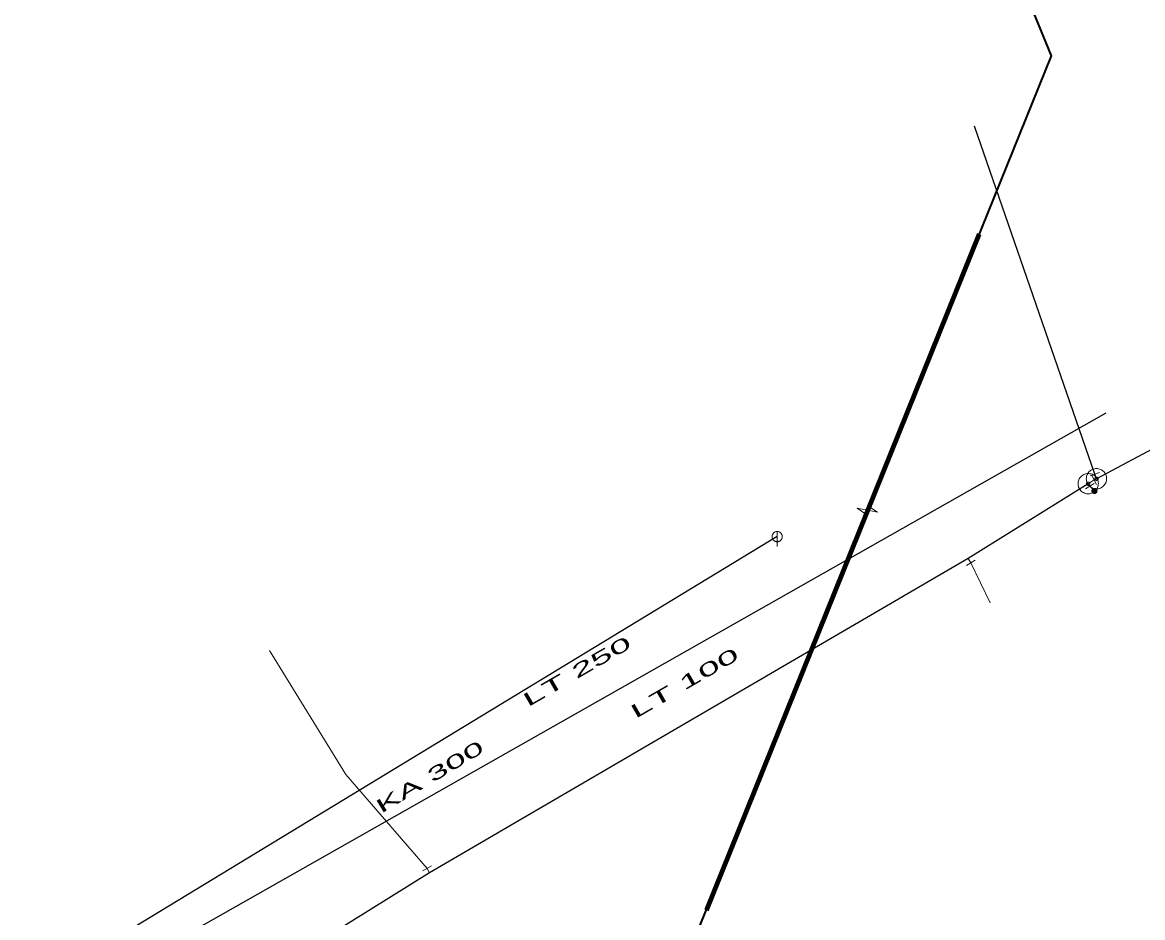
# Model space of a CAD drawing. Extents: x -687468 to -685917, y -974192 to -973456.
# Drawn here: x -686202 to -686146.9, y -973571.9 to -973527.9 of the extents above; entities that cross this region are included whole.
import ezdxf
from ezdxf.enums import TextEntityAlignment as Align

# ---------------------------------------------------------------- set-up
doc = ezdxf.new("R2010")
doc.units = 0
doc.header["$LTSCALE"] = 0.27
for name, color, linetype, lineweight in [('1', 7, 'Continuous', 13), ('13', 7, 'Continuous', 13), ('14', 7, 'Continuous', 25), ('17', 7, 'Continuous', 25), ('22', 7, 'Continuous', 13), ('3', 7, 'Continuous', 106), ('34', 7, 'Continuous', 13), ('47', 7, 'Continuous', 13), ('9', 7, 'Continuous', 13)]:
    doc.layers.add(name, color=color, linetype=linetype, lineweight=lineweight)

msp = doc.modelspace()

# ---------------------------------------------------------------- linework, layer by layer
at = {"layer": '13'}
msp.add_line((-686155.338, -973554.482), (-686154.39, -973556.449), dxfattribs=at)
msp.add_lwpolyline([(-686182.105, -973569.523), (-686186.109, -973564.899), (-686189.87, -973558.8)], dxfattribs=at)
at = {"layer": '14', "lineweight": 13}
for p, q in [((-686149.149, -973550.34), (-686149.229, -973550.109)), ((-686149.149, -973550.34), (-686149.259, -973550.399)), ((-686155.338, -973554.482), (-686155.47, -973554.27)), ((-686182.105, -973569.523), (-686181.98, -973569.739))]:
    msp.add_line(p, q, dxfattribs=at)
at = {"layer": '14'}
msp.add_line((-686164.87, -973553.19), (-686200.73, -973574.96), dxfattribs=at)
at = {"layer": '14', "lineweight": 13}
msp.add_lwpolyline([(-686149.259, -973550.399), (-686149.557, -973550.584), (-686149.48, -973550.709), (-686149.249, -973550.939)], dxfattribs=at)
at = {"layer": '17'}
msp.add_line((-686130.129, -973540.219), (-686149.149, -973550.34), dxfattribs=at)
at = {"layer": '17', "lineweight": 35}
for points in [[(-686159.37, -973510.05), (-686151.386, -973529.517), (-686160.425, -973551.891)], [(-686160.425, -973551.891), (-686169.469, -973574.282), (-686122.999, -973646.384), (-686098.932, -973712.353), (-686089.329, -973782.048), (-686297.791, -974027.806), (-686326.807, -974076.614), (-686379.703, -974100.561), (-686411.584, -974111.413)]]:
    msp.add_lwpolyline(points, dxfattribs=at)
at = {"layer": '17'}
for points in [[(-686149.149, -973550.34), (-686149.229, -973550.109), (-686155.149, -973532.979)], [(-686148.68, -973547.12), (-686199.359, -973575.84), (-686213.05, -973583.12), (-686218.669, -973575.249)], [(-686149.557, -973550.584), (-686155.469, -973554.27), (-686181.98, -973569.739), (-686198.489, -973580.019)]]:
    msp.add_lwpolyline(points, dxfattribs=at)
at = {"layer": '22'}
msp.add_line((-686164.869, -973552.938), (-686164.87, -973553.681), dxfattribs=at)
msp.add_lwpolyline([(-686164.618, -973553.19), (-686164.619, -973553.164), (-686164.623, -973553.138), (-686164.629, -973553.112), (-686164.639, -973553.088), (-686164.651, -973553.064), (-686164.665, -973553.042), (-686164.682, -973553.021), (-686164.7, -973553.003), (-686164.721, -973552.986), (-686164.743, -973552.972), (-686164.767, -973552.96), (-686164.791, -973552.95), (-686164.817, -973552.944), (-686164.843, -973552.94), (-686164.869, -973552.938), (-686164.895, -973552.939), (-686164.921, -973552.943), (-686164.947, -973552.949), (-686164.972, -973552.959), (-686164.995, -973552.971), (-686165.017, -973552.985), (-686165.038, -973553.002), (-686165.056, -973553.02), (-686165.073, -973553.041), (-686165.087, -973553.063), (-686165.099, -973553.087), (-686165.109, -973553.111), (-686165.116, -973553.137), (-686165.12, -973553.163), (-686165.122, -973553.189), (-686165.121, -973553.215), (-686165.117, -973553.241), (-686165.11, -973553.267), (-686165.1, -973553.292), (-686165.088, -973553.315), (-686165.074, -973553.337), (-686165.057, -973553.358), (-686165.039, -973553.376), (-686165.018, -973553.393), (-686164.996, -973553.407), (-686164.973, -973553.419), (-686164.948, -973553.429), (-686164.922, -973553.436), (-686164.896, -973553.44), (-686164.87, -973553.441), (-686164.844, -973553.441), (-686164.818, -973553.437), (-686164.792, -973553.43), (-686164.768, -973553.42), (-686164.744, -973553.408), (-686164.722, -973553.394), (-686164.701, -973553.377), (-686164.683, -973553.359), (-686164.666, -973553.338), (-686164.652, -973553.316), (-686164.64, -973553.293), (-686164.63, -973553.268), (-686164.624, -973553.242), (-686164.62, -973553.216)], close=True, dxfattribs=at)
at = {"layer": '3'}
msp.add_line((-686168.344, -973571.57), (-686154.923, -973538.295), dxfattribs=at)
at = {"layer": '3', "lineweight": 100}
msp.add_line((-686168.344, -973571.57), (-686154.923, -973538.295), dxfattribs=at)
at = {"layer": '34'}
for p, q in [((-686149.463, -973550.19), (-686148.994, -973550.027)), ((-686149.141, -973550.617), (-686149.376, -973550.18)), ((-686149.69, -973550.84), (-686149.269, -973550.577)), ((-686155.548, -973554.613), (-686155.127, -973554.35)), ((-686182.319, -973569.647), (-686181.89, -973569.398))]:
    msp.add_line(p, q, dxfattribs=at)
at = {"layer": '47'}
msp.add_line((-686160.925, -973551.794), (-686160.5, -973552.077), dxfattribs=at)
for points in [[(-686149.132, -973550.32), (-686149.162, -973550.277), (-686149.196, -973550.237), (-686149.234, -973550.202), (-686149.275, -973550.17), (-686149.32, -973550.143), (-686149.368, -973550.121), (-686149.417, -973550.104), (-686149.468, -973550.092), (-686149.52, -973550.085), (-686149.572, -973550.084), (-686149.625, -973550.088), (-686149.676, -973550.099), (-686149.726, -973550.113), (-686149.774, -973550.134), (-686149.82, -973550.159), (-686149.863, -973550.189), (-686149.903, -973550.223), (-686149.939, -973550.262), (-686149.97, -973550.302), (-686149.997, -973550.347), (-686150.019, -973550.395), (-686150.037, -973550.445), (-686150.049, -973550.496), (-686150.056, -973550.547), (-686150.056, -973550.599), (-686150.052, -973550.652), (-686150.042, -973550.704), (-686150.027, -973550.753), (-686150.006, -973550.801), (-686149.981, -973550.847), (-686149.951, -973550.89), (-686149.917, -973550.93), (-686149.879, -973550.966), (-686149.838, -973550.997), (-686149.793, -973551.024), (-686149.746, -973551.047), (-686149.696, -973551.064), (-686149.645, -973551.076), (-686149.593, -973551.083), (-686149.541, -973551.083), (-686149.488, -973551.079), (-686149.437, -973551.07), (-686149.387, -973551.054), (-686149.339, -973551.033), (-686149.293, -973551.008), (-686149.25, -973550.978), (-686149.21, -973550.944), (-686149.175, -973550.907), (-686149.143, -973550.865), (-686149.116, -973550.82), (-686149.093, -973550.773), (-686149.077, -973550.723), (-686149.065, -973550.672), (-686149.058, -973550.62), (-686149.057, -973550.568), (-686149.061, -973550.515), (-686149.071, -973550.465), (-686149.086, -973550.414), (-686149.107, -973550.366)], [(-686148.691, -973550.139), (-686148.714, -973550.092), (-686148.743, -973550.048), (-686148.775, -973550.008), (-686148.812, -973549.97), (-686148.853, -973549.937), (-686148.897, -973549.908), (-686148.943, -973549.885), (-686148.992, -973549.866), (-686149.042, -973549.851), (-686149.094, -973549.843), (-686149.146, -973549.839), (-686149.198, -973549.843), (-686149.25, -973549.85), (-686149.301, -973549.864), (-686149.349, -973549.882), (-686149.396, -973549.905), (-686149.44, -973549.934), (-686149.481, -973549.967), (-686149.518, -973550.003), (-686149.551, -973550.044), (-686149.58, -973550.088), (-686149.604, -973550.134), (-686149.623, -973550.183), (-686149.638, -973550.233), (-686149.645, -973550.285), (-686149.649, -973550.337), (-686149.646, -973550.39), (-686149.638, -973550.441), (-686149.624, -973550.492), (-686149.606, -973550.54), (-686149.583, -973550.587), (-686149.554, -973550.631), (-686149.522, -973550.673), (-686149.485, -973550.709), (-686149.444, -973550.742), (-686149.401, -973550.772), (-686149.354, -973550.796), (-686149.306, -973550.815), (-686149.255, -973550.829), (-686149.203, -973550.836), (-686149.151, -973550.84), (-686149.099, -973550.838), (-686149.047, -973550.829), (-686148.996, -973550.815), (-686148.948, -973550.797), (-686148.901, -973550.774), (-686148.857, -973550.745), (-686148.816, -973550.713), (-686148.779, -973550.676), (-686148.746, -973550.635), (-686148.716, -973550.592), (-686148.693, -973550.546), (-686148.674, -973550.497), (-686148.66, -973550.446), (-686148.652, -973550.394), (-686148.648, -973550.342), (-686148.651, -973550.29), (-686148.659, -973550.238), (-686148.673, -973550.187)], [(-686149.073, -973550.307), (-686149.077, -973550.298), (-686149.082, -973550.292), (-686149.087, -973550.285), (-686149.093, -973550.279), (-686149.1, -973550.273), (-686149.107, -973550.269), (-686149.115, -973550.265), (-686149.123, -973550.262), (-686149.131, -973550.26), (-686149.14, -973550.258), (-686149.148, -973550.258), (-686149.157, -973550.258), (-686149.165, -973550.259), (-686149.173, -973550.261), (-686149.181, -973550.264), (-686149.19, -973550.268), (-686149.196, -973550.273), (-686149.203, -973550.278), (-686149.209, -973550.284), (-686149.215, -973550.291), (-686149.219, -973550.298), (-686149.223, -973550.306), (-686149.226, -973550.314), (-686149.229, -973550.322), (-686149.23, -973550.331), (-686149.23, -973550.339), (-686149.23, -973550.348), (-686149.229, -973550.356), (-686149.227, -973550.364), (-686149.224, -973550.372), (-686149.22, -973550.381), (-686149.215, -973550.387), (-686149.21, -973550.394), (-686149.204, -973550.4), (-686149.197, -973550.406), (-686149.191, -973550.41), (-686149.182, -973550.414), (-686149.174, -973550.417), (-686149.166, -973550.42), (-686149.157, -973550.421), (-686149.149, -973550.421), (-686149.14, -973550.421), (-686149.132, -973550.42), (-686149.124, -973550.418), (-686149.116, -973550.415), (-686149.107, -973550.411), (-686149.101, -973550.406), (-686149.094, -973550.401), (-686149.088, -973550.395), (-686149.082, -973550.388), (-686149.078, -973550.382), (-686149.074, -973550.373), (-686149.071, -973550.365), (-686149.069, -973550.357), (-686149.067, -973550.348), (-686149.067, -973550.34), (-686149.067, -973550.331), (-686149.068, -973550.323), (-686149.07, -973550.315)], [(-686149.487, -973550.54), (-686149.492, -973550.533), (-686149.497, -973550.527), (-686149.503, -973550.521), (-686149.51, -973550.516), (-686149.518, -973550.511), (-686149.526, -973550.508), (-686149.534, -973550.505), (-686149.542, -973550.503), (-686149.551, -973550.502), (-686149.559, -973550.502), (-686149.568, -973550.502), (-686149.576, -973550.504), (-686149.584, -973550.507), (-686149.592, -973550.509), (-686149.6, -973550.514), (-686149.607, -973550.519), (-686149.613, -973550.524), (-686149.619, -973550.53), (-686149.624, -973550.537), (-686149.629, -973550.545), (-686149.632, -973550.553), (-686149.635, -973550.561), (-686149.637, -973550.569), (-686149.639, -973550.578), (-686149.638, -973550.586), (-686149.638, -973550.595), (-686149.636, -973550.603), (-686149.633, -973550.611), (-686149.631, -973550.619), (-686149.626, -973550.627), (-686149.621, -973550.634), (-686149.616, -973550.64), (-686149.61, -973550.646), (-686149.603, -973550.651), (-686149.595, -973550.656), (-686149.588, -973550.66), (-686149.579, -973550.662), (-686149.571, -973550.664), (-686149.562, -973550.666), (-686149.554, -973550.665), (-686149.545, -973550.665), (-686149.537, -973550.663), (-686149.529, -973550.66), (-686149.521, -973550.658), (-686149.513, -973550.653), (-686149.506, -973550.648), (-686149.5, -973550.643), (-686149.494, -973550.637), (-686149.489, -973550.63), (-686149.484, -973550.622), (-686149.48, -973550.615), (-686149.478, -973550.606), (-686149.476, -973550.598), (-686149.475, -973550.589), (-686149.475, -973550.581), (-686149.475, -973550.572), (-686149.477, -973550.564), (-686149.48, -973550.556), (-686149.482, -973550.548)]]:
    msp.add_lwpolyline(points, close=True, dxfattribs=at)
msp.add_lwpolyline([(-686160.925, -973551.794), (-686159.924, -973551.987), (-686160.349, -973551.704)], dxfattribs=at)
at = {"layer": '9'}
for points in [[(-686149.122, -973550.939), (-686149.124, -973550.926), (-686149.125, -973550.913), (-686149.129, -973550.9), (-686149.134, -973550.888), (-686149.139, -973550.876), (-686149.147, -973550.865), (-686149.154, -973550.855), (-686149.164, -973550.845), (-686149.174, -973550.837), (-686149.186, -973550.83), (-686149.198, -973550.824), (-686149.21, -973550.819), (-686149.223, -973550.816), (-686149.235, -973550.814), (-686149.249, -973550.813), (-686149.262, -973550.814), (-686149.274, -973550.816), (-686149.288, -973550.819), (-686149.299, -973550.824), (-686149.311, -973550.83), (-686149.323, -973550.837), (-686149.333, -973550.845), (-686149.343, -973550.855), (-686149.35, -973550.865), (-686149.358, -973550.876), (-686149.364, -973550.888), (-686149.369, -973550.9), (-686149.372, -973550.913), (-686149.374, -973550.926), (-686149.375, -973550.939), (-686149.374, -973550.952), (-686149.372, -973550.965), (-686149.369, -973550.978), (-686149.364, -973550.99), (-686149.358, -973551.002), (-686149.35, -973551.013), (-686149.343, -973551.023), (-686149.333, -973551.033), (-686149.323, -973551.041), (-686149.311, -973551.048), (-686149.299, -973551.054), (-686149.288, -973551.059), (-686149.274, -973551.062), (-686149.262, -973551.064), (-686149.249, -973551.065), (-686149.235, -973551.064), (-686149.223, -973551.062), (-686149.21, -973551.059), (-686149.198, -973551.054), (-686149.186, -973551.048), (-686149.174, -973551.041), (-686149.164, -973551.033), (-686149.154, -973551.023), (-686149.147, -973551.013), (-686149.139, -973551.002), (-686149.134, -973550.99), (-686149.129, -973550.978), (-686149.125, -973550.965), (-686149.124, -973550.952)], [(-686149.142, -973550.939), (-686149.142, -973550.928), (-686149.144, -973550.917), (-686149.147, -973550.906), (-686149.152, -973550.896), (-686149.157, -973550.886), (-686149.163, -973550.877), (-686149.169, -973550.868), (-686149.178, -973550.86), (-686149.186, -973550.853), (-686149.196, -973550.847), (-686149.206, -973550.842), (-686149.215, -973550.838), (-686149.227, -973550.835), (-686149.237, -973550.833), (-686149.249, -973550.833), (-686149.26, -973550.833), (-686149.271, -973550.835), (-686149.282, -973550.838), (-686149.291, -973550.842), (-686149.301, -973550.847), (-686149.311, -973550.853), (-686149.32, -973550.86), (-686149.328, -973550.868), (-686149.335, -973550.877), (-686149.34, -973550.886), (-686149.345, -973550.896), (-686149.35, -973550.906), (-686149.353, -973550.917), (-686149.355, -973550.928), (-686149.355, -973550.939), (-686149.355, -973550.95), (-686149.353, -973550.961), (-686149.35, -973550.972), (-686149.345, -973550.982), (-686149.34, -973550.992), (-686149.335, -973551.001), (-686149.328, -973551.01), (-686149.32, -973551.018), (-686149.311, -973551.025), (-686149.301, -973551.031), (-686149.291, -973551.036), (-686149.282, -973551.04), (-686149.271, -973551.043), (-686149.26, -973551.045), (-686149.249, -973551.045), (-686149.237, -973551.045), (-686149.227, -973551.043), (-686149.215, -973551.04), (-686149.206, -973551.036), (-686149.196, -973551.031), (-686149.186, -973551.025), (-686149.178, -973551.018), (-686149.169, -973551.01), (-686149.163, -973551.001), (-686149.157, -973550.992), (-686149.152, -973550.982), (-686149.147, -973550.972), (-686149.144, -973550.961), (-686149.142, -973550.95)], [(-686149.161, -973550.939), (-686149.163, -973550.93), (-686149.164, -973550.921), (-686149.166, -973550.912), (-686149.169, -973550.904), (-686149.174, -973550.896), (-686149.179, -973550.888), (-686149.184, -973550.881), (-686149.191, -973550.875), (-686149.198, -973550.869), (-686149.206, -973550.864), (-686149.213, -973550.86), (-686149.222, -973550.857), (-686149.23, -973550.854), (-686149.24, -973550.853), (-686149.249, -973550.852), (-686149.257, -973550.853), (-686149.267, -973550.854), (-686149.276, -973550.857), (-686149.284, -973550.86), (-686149.291, -973550.864), (-686149.299, -973550.869), (-686149.306, -973550.875), (-686149.313, -973550.881), (-686149.318, -973550.888), (-686149.323, -973550.896), (-686149.328, -973550.904), (-686149.331, -973550.912), (-686149.333, -973550.921), (-686149.335, -973550.93), (-686149.336, -973550.939), (-686149.335, -973550.948), (-686149.333, -973550.957), (-686149.331, -973550.966), (-686149.328, -973550.974), (-686149.323, -973550.982), (-686149.318, -973550.99), (-686149.313, -973550.997), (-686149.306, -973551.003), (-686149.299, -973551.009), (-686149.291, -973551.014), (-686149.284, -973551.018), (-686149.276, -973551.021), (-686149.267, -973551.024), (-686149.257, -973551.025), (-686149.249, -973551.026), (-686149.24, -973551.025), (-686149.23, -973551.024), (-686149.222, -973551.021), (-686149.213, -973551.018), (-686149.206, -973551.014), (-686149.198, -973551.009), (-686149.191, -973551.003), (-686149.184, -973550.997), (-686149.179, -973550.99), (-686149.174, -973550.982), (-686149.169, -973550.974), (-686149.166, -973550.966), (-686149.164, -973550.957), (-686149.163, -973550.948)], [(-686149.181, -973550.939), (-686149.181, -973550.932), (-686149.184, -973550.925), (-686149.184, -973550.918), (-686149.188, -973550.912), (-686149.191, -973550.906), (-686149.195, -973550.9), (-686149.198, -973550.894), (-686149.203, -973550.889), (-686149.21, -973550.885), (-686149.215, -973550.881), (-686149.222, -973550.878), (-686149.228, -973550.875), (-686149.235, -973550.874), (-686149.242, -973550.872), (-686149.249, -973550.872), (-686149.255, -973550.872), (-686149.262, -973550.874), (-686149.269, -973550.875), (-686149.276, -973550.878), (-686149.282, -973550.881), (-686149.288, -973550.885), (-686149.294, -973550.889), (-686149.299, -973550.894), (-686149.303, -973550.9), (-686149.306, -973550.906), (-686149.309, -973550.912), (-686149.313, -973550.918), (-686149.315, -973550.925), (-686149.316, -973550.932), (-686149.316, -973550.939), (-686149.316, -973550.946), (-686149.315, -973550.953), (-686149.313, -973550.96), (-686149.309, -973550.966), (-686149.306, -973550.973), (-686149.303, -973550.978), (-686149.299, -973550.984), (-686149.294, -973550.989), (-686149.288, -973550.993), (-686149.282, -973550.997), (-686149.276, -973551), (-686149.269, -973551.003), (-686149.262, -973551.005), (-686149.255, -973551.006), (-686149.249, -973551.006), (-686149.242, -973551.006), (-686149.235, -973551.005), (-686149.228, -973551.003), (-686149.222, -973551), (-686149.215, -973550.997), (-686149.21, -973550.993), (-686149.203, -973550.989), (-686149.198, -973550.984), (-686149.195, -973550.978), (-686149.191, -973550.973), (-686149.188, -973550.966), (-686149.184, -973550.96), (-686149.184, -973550.953), (-686149.181, -973550.946)], [(-686149.201, -973550.939), (-686149.201, -973550.934), (-686149.203, -973550.929), (-686149.203, -973550.924), (-686149.206, -973550.92), (-686149.208, -973550.915), (-686149.211, -973550.911), (-686149.213, -973550.908), (-686149.218, -973550.904), (-686149.22, -973550.901), (-686149.225, -973550.898), (-686149.23, -973550.896), (-686149.233, -973550.894), (-686149.239, -973550.893), (-686149.244, -973550.892), (-686149.249, -973550.892), (-686149.254, -973550.892), (-686149.259, -973550.893), (-686149.264, -973550.894), (-686149.267, -973550.896), (-686149.272, -973550.898), (-686149.277, -973550.901), (-686149.281, -973550.904), (-686149.284, -973550.908), (-686149.286, -973550.911), (-686149.289, -973550.915), (-686149.291, -973550.92), (-686149.294, -973550.924), (-686149.294, -973550.929), (-686149.296, -973550.934), (-686149.296, -973550.939), (-686149.296, -973550.944), (-686149.294, -973550.949), (-686149.294, -973550.954), (-686149.291, -973550.958), (-686149.289, -973550.963), (-686149.286, -973550.967), (-686149.284, -973550.971), (-686149.281, -973550.974), (-686149.277, -973550.977), (-686149.272, -973550.98), (-686149.267, -973550.982), (-686149.264, -973550.984), (-686149.259, -973550.985), (-686149.254, -973550.986), (-686149.249, -973550.986), (-686149.244, -973550.986), (-686149.239, -973550.985), (-686149.233, -973550.984), (-686149.23, -973550.982), (-686149.225, -973550.98), (-686149.22, -973550.977), (-686149.218, -973550.974), (-686149.213, -973550.971), (-686149.211, -973550.967), (-686149.208, -973550.963), (-686149.206, -973550.958), (-686149.203, -973550.954), (-686149.203, -973550.949), (-686149.201, -973550.944)], [(-686149.222, -973550.939), (-686149.222, -973550.936), (-686149.222, -973550.933), (-686149.223, -973550.931), (-686149.223, -973550.928), (-686149.225, -973550.925), (-686149.227, -973550.923), (-686149.228, -973550.921), (-686149.23, -973550.919), (-686149.233, -973550.917), (-686149.235, -973550.915), (-686149.237, -973550.914), (-686149.24, -973550.913), (-686149.242, -973550.912), (-686149.245, -973550.912), (-686149.249, -973550.912), (-686149.252, -973550.912), (-686149.255, -973550.912), (-686149.257, -973550.913), (-686149.26, -973550.914), (-686149.262, -973550.915), (-686149.264, -973550.917), (-686149.267, -973550.919), (-686149.269, -973550.921), (-686149.271, -973550.923), (-686149.272, -973550.925), (-686149.274, -973550.928), (-686149.274, -973550.931), (-686149.276, -973550.933), (-686149.276, -973550.936), (-686149.277, -973550.939), (-686149.276, -973550.942), (-686149.276, -973550.945), (-686149.274, -973550.948), (-686149.274, -973550.95), (-686149.272, -973550.953), (-686149.271, -973550.955), (-686149.269, -973550.958), (-686149.267, -973550.96), (-686149.264, -973550.961), (-686149.262, -973550.963), (-686149.26, -973550.964), (-686149.257, -973550.965), (-686149.255, -973550.966), (-686149.252, -973550.966), (-686149.249, -973550.967), (-686149.245, -973550.966), (-686149.242, -973550.966), (-686149.24, -973550.965), (-686149.237, -973550.964), (-686149.235, -973550.963), (-686149.233, -973550.961), (-686149.23, -973550.96), (-686149.228, -973550.958), (-686149.227, -973550.955), (-686149.225, -973550.953), (-686149.223, -973550.95), (-686149.223, -973550.948), (-686149.222, -973550.945), (-686149.222, -973550.942)], [(-686149.24, -973550.939), (-686149.24, -973550.938), (-686149.24, -973550.937), (-686149.242, -973550.937), (-686149.242, -973550.936), (-686149.242, -973550.935), (-686149.242, -973550.934), (-686149.242, -973550.934), (-686149.244, -973550.933), (-686149.244, -973550.933), (-686149.245, -973550.932), (-686149.245, -973550.932), (-686149.247, -973550.932), (-686149.247, -973550.931), (-686149.247, -973550.931), (-686149.249, -973550.931), (-686149.25, -973550.931), (-686149.25, -973550.931), (-686149.25, -973550.932), (-686149.252, -973550.932), (-686149.252, -973550.932), (-686149.254, -973550.933), (-686149.254, -973550.933), (-686149.255, -973550.934), (-686149.255, -973550.934), (-686149.255, -973550.935), (-686149.255, -973550.936), (-686149.257, -973550.937), (-686149.257, -973550.937), (-686149.257, -973550.938), (-686149.257, -973550.939), (-686149.257, -973550.94), (-686149.257, -973550.941), (-686149.257, -973550.941), (-686149.255, -973550.942), (-686149.255, -973550.943), (-686149.255, -973550.944), (-686149.255, -973550.944), (-686149.254, -973550.945), (-686149.254, -973550.945), (-686149.252, -973550.946), (-686149.252, -973550.946), (-686149.25, -973550.947), (-686149.25, -973550.947), (-686149.25, -973550.947), (-686149.249, -973550.947), (-686149.247, -973550.947), (-686149.247, -973550.947), (-686149.247, -973550.947), (-686149.245, -973550.946), (-686149.245, -973550.946), (-686149.244, -973550.945), (-686149.244, -973550.945), (-686149.242, -973550.944), (-686149.242, -973550.944), (-686149.242, -973550.943), (-686149.242, -973550.942), (-686149.242, -973550.941), (-686149.24, -973550.941), (-686149.24, -973550.94)]]:
    msp.add_lwpolyline(points, close=True, dxfattribs=at)

# ---------------------------------------------------------------- texts
at = {"layer": '1'}
for s, rotation, width, p in [('LT 250', 30, 2.15, (-686174.562, -973560.107)), ('LT 100', 30, 2.15, (-686169.266, -973560.678)), ('KA 300', 31, 2.05, (-686181.802, -973565.294))]:
    msp.add_text(s, height=0.6667, rotation=rotation, dxfattribs=dict(at, width=width)).set_placement(p, align=Align.CENTER)

doc.saveas('drawing.dxf')
